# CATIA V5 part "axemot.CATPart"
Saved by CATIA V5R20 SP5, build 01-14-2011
Part number: axemot
Bounding box of the stored display mesh (mm): x -205.841 to 14.159, y -20.994 to 20.994, z -20.994 to 20.994
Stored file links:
  D:\thinkmotion-MPB\Dropbox\IAO\IAO_2010\iao\IAO OK\IAO_2010_1447_melguidj\Catia_1447_melguidj\axemot.CATPart
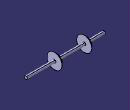
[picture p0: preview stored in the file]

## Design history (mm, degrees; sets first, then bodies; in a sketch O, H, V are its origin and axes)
Body1 (main body)
  DatumCurve1
  DatumCurve2
  Sketch1 on zx-plane, origin (0, 0, 0), H (-1, 0, 0), V (0, 0, 1)
    point P1 (-14.159, 0)
    line L1 (-14.159, 0) -> (-14.159, 4)
    line L2 (-14.159, 4) -> (66.381, 4)
    line L3 (66.381, 4) -> (66.381, 21)
    line L4 (66.381, 21) -> (73.381, 14)
    line L5 (73.381, 14) -> (73.381, 4)
    point P6 (73.381, 4)
    line L6 (73.381, 4) -> (149.841, 4)
    line L7 (149.841, 4) -> (149.841, 21)
    line L8 (149.841, 21) -> (156.841, 14)
    line L9 (156.841, 14) -> (156.841, 4)
    point P10 (156.841, 4)
    line L10 (156.841, 4) -> (205.841, 4)
    line L11 (205.841, 4) -> (205.841, 0)
    point P12 (205.841, 0)
    line L12 (205.841, 0) -> (-14.159, 0)
    reference intersected line E1 through (205.841, 0) direction (0, -1) from face of DatumSurface7
    length L1 = 4
    angle L6 L4 = 45
    length L5 = 10
    distance L3 L5 = 7
    distance L7 L9 = 7
    length L9 = 10
    distance L1 L11 = 220
    distance E1 L9 = 49
    distance L5 L7 = 76.46
    coincidence: P1 H, P6 L2, P10 L2, P12 H
    vertical: L1 V, L3 V, L5 V, L7 V, L9 V, L11 V
    horizontal: L2 H, L6 H, L10 H, L12 H
    parallelism: L8 L4
  Shaft1: profile Sketch1, axis Sketch1.L12, angle 360
  DatumCurve3
  DatumSurface1 to DatumSurface7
